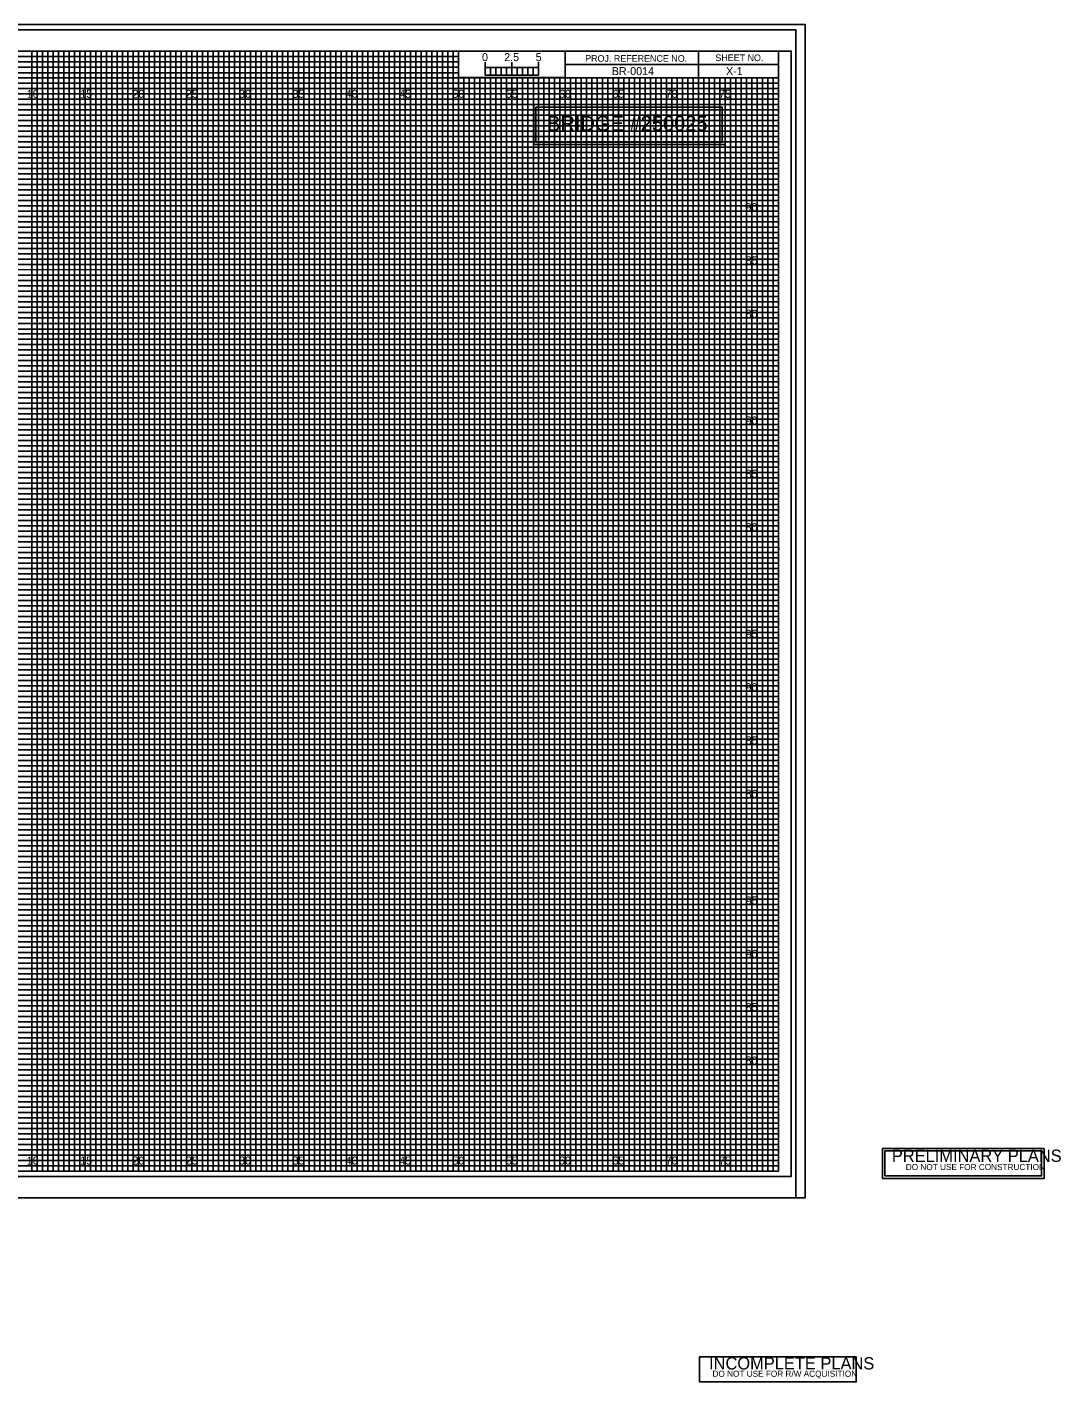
# Model space of a CAD drawing. Extents: x -8 to 533, y -20 to 768.
# Drawn here: x 89.5 to 186.5, y -19.8 to 107.2 of the extents above; entities that cross this region are included whole.
import ezdxf

# ---------------------------------------------------------------- set-up
doc = ezdxf.new("R2010")
doc.units = 0
for name, color, linetype in [('Old_Level_1', 7, 'Continuous'), ('Old_Level_34', 7, 'Continuous'), ('Prop Grid Mask', 7, 'Continuous'), ('Prop XS Bar Scale Labels', 7, 'Continuous'), ('Prop XS Elevation Labels', 7, 'Continuous'), ('Prop XS Offset Labels', 7, 'Continuous'), ('Prop XS Project Number', 7, 'Continuous'), ('Prop XS Sheet Number', 7, 'Continuous'), ('Sheet Cross Section CELL', 7, 'Continuous'), ('Sheet Cross Section Grid Major CELL', 7, 'Continuous'), ('Sheet Cross Section Grid Middle CELL', 7, 'Continuous'), ('Sheet Cross Section Grid Minor 1 CELL', 7, 'Continuous'), ('Sheet Cross Section Grid Minor 2 CELL', 7, 'Continuous'), ('Sheet Cross Section Scale CELL', 7, 'Continuous'), ('Sheet Cutting Line CELL', 7, 'Continuous'), ('Sheet DOT Grid CELL', 7, 'Continuous'), ('Sheet Plot Border Inside CELL', 7, 'Continuous'), ('Sheet Plot Border Outside CELL', 7, 'Continuous'), ('Sheet Sticker Incomplete CELL', 7, 'Continuous'), ('Sheet Sticker Preliminary CELL', 7, 'Continuous'), ('WEI Plot Border', 7, 'Continuous')]:
    doc.layers.add(name, color=color, linetype=linetype)

msp = doc.modelspace()

# ---------------------------------------------------------------- linework, layer by layer
at = {"layer": 'Old_Level_34'}
msp.add_lwpolyline([(137.26, 99.75), (154.74, 99.75), (154.74, 96.46), (137.26, 96.46)], close=True, dxfattribs=at)
at = {"layer": 'Prop Grid Mask'}
for points in [[(137.08, 100), (155, 100), (155, 96.24), (137.08, 96.24)], [(184.92, 2.13), (169.77, 2.13), (169.77, -0.7), (184.92, -0.7)]]:
    msp.add_lwpolyline(points, close=True, dxfattribs=at)
at = {"layer": 'Sheet Cross Section CELL'}
for p, q in [((152.5, 105), (152.5, 102.5)), ((152.5, 102.5), (152.5, 105)), ((160, 103.75), (140, 103.75)), ((140, 103.75), (140, 102.5)), ((140, 102.5), (160, 102.5))]:
    msp.add_line(p, q, dxfattribs=at)
for points in [[(160, 105), (0, 105), (0, 0), (160, 0)], [(140, 105), (130, 105), (130, 102.52), (140, 102.52)], [(160, 105), (140, 105), (140, 102.5), (160, 102.5)]]:
    msp.add_lwpolyline(points, close=True, dxfattribs=at)
at = {"layer": 'Sheet Cross Section Grid Major CELL'}
for p, q in [((95, 105), (90, 105)), ((90, 105), (90, 0)), ((95, 0), (95, 105)), ((105, 105), (100, 105)), ((100, 105), (100, 0)), ((105, 0), (105, 105)), ((115, 105), (110, 105)), ((110, 105), (110, 0)), ((115, 0), (115, 105)), ((125, 105), (120, 105)), ((120, 105), (120, 0)), ((125, 0), (125, 105)), ((130, 105), (130, 0)), ((135, 0), (135, 102.5)), ((145, 102.5), (140, 102.5)), ((140, 102.5), (140, 0)), ((145, 0), (145, 102.5)), ((155, 102.5), (150, 102.5)), ((150, 102.5), (150, 0)), ((155, 0), (155, 102.5)), ((90, 0), (85, 0)), ((100, 0), (95, 0)), ((110, 0), (105, 0)), ((120, 0), (115, 0)), ((130, 0), (125, 0)), ((140, 0), (135, 0)), ((150, 0), (145, 0)), ((160, 0), (155, 0)), ((160, 0), (160, 0))]:
    msp.add_line(p, q, dxfattribs=at)
for points in [[(0, 100), (160, 100), (160, 95), (0, 95)], [(0, 90), (160, 90), (160, 85), (0, 85)], [(0, 80), (160, 80), (160, 75), (0, 75)], [(0, 70), (160, 70), (160, 65), (0, 65)], [(0, 60), (160, 60), (160, 55), (0, 55)], [(0, 50), (160, 50), (160, 45), (0, 45)], [(0, 40), (160, 40), (160, 35), (0, 35)], [(0, 30), (160, 30), (160, 25), (0, 25)], [(0, 20), (160, 20), (160, 15), (0, 15)], [(0, 10), (160, 10), (160, 5), (0, 5)]]:
    msp.add_lwpolyline(points, dxfattribs=at)
at = {"layer": 'Sheet Cross Section Grid Middle CELL'}
for points in [[(87.5, 105), (92.5, 105), (92.5, 0), (97.5, 0), (97.5, 105), (102.5, 105), (102.5, 0), (107.5, 0), (107.5, 105), (112.5, 105), (112.5, 0), (117.5, 0), (117.5, 105), (122.5, 105), (122.5, 0), (127.5, 0), (127.5, 105), (129.97, 105), (130, 105), (130, 102.5), (132.5, 102.5), (132.5, 0), (137.5, 0), (137.5, 102.5), (142.5, 102.5), (142.5, 0), (147.5, 0), (147.5, 102.5), (152.5, 102.5), (152.5, 0), (157.5, 0), (157.5, 102.5)], [(0, 102.5), (137.5, 102.5)], [(0, 92.5), (160, 92.5), (160, 97.5), (0, 97.5)], [(0, 82.5), (160, 82.5), (160, 87.5), (0, 87.5)], [(0, 72.5), (160, 72.5), (160, 77.5), (0, 77.5)], [(0, 62.5), (160, 62.5), (160, 67.5), (0, 67.5)], [(0, 52.5), (160, 52.5), (160, 57.5), (0, 57.5)], [(0, 42.5), (160, 42.5), (160, 47.5), (0, 47.5)], [(0, 32.5), (160, 32.5), (160, 37.5), (0, 37.5)], [(0, 22.5), (160, 22.5), (160, 27.5), (0, 27.5)], [(0, 12.5), (160, 12.5), (160, 17.5), (0, 17.5)], [(0, 2.5), (160, 2.5), (160, 7.5), (0, 7.5)]]:
    msp.add_lwpolyline(points, dxfattribs=at)
at = {"layer": 'Sheet Cross Section Grid Minor 1 CELL'}
for p, q in [((0, 104.5), (130, 104.5)), ((130, 104.5), (130, 103.99)), ((130, 103.99), (0, 103.99)), ((0, 103.5), (130, 103.5)), ((130, 102.95), (0, 102.95)), ((130, 103.5), (130, 102.95)), ((0, 102), (160, 102))]:
    msp.add_line(p, q, dxfattribs=at)
for points in [[(0, 101.5), (135, 101.5), (160, 101.5), (160, 101), (0, 101)], [(0, 100.5), (160, 100.5), (160, 99.5), (0, 99.5)], [(0, 99), (160, 99), (160, 98.5), (0, 98.49)], [(0, 98), (160, 98), (160, 97), (0, 97)], [(0, 96.5), (160, 96.5), (160, 96), (0, 96)], [(0, 95.5), (160, 95.5), (160, 94.5), (0, 94.5)], [(0, 94), (160, 94), (160, 93.5), (0, 93.5)], [(0, 93), (160, 93), (160, 92), (0, 92)], [(0, 91.5), (160, 91.5), (160, 91), (0, 91)], [(0, 90.5), (160, 90.5), (160, 89.5), (0, 89.5)], [(0, 89), (160, 89), (160, 88.5), (0, 88.5)], [(0, 88), (160, 88), (160, 86.98), (160, 86.5), (160, 86), (0, 86)], [(0, 87), (160, 87), (160, 86.5), (0, 86.5)], [(0, 85.5), (160, 85.5), (160, 84.5), (0, 84.52)], [(0, 84.52), (160, 84.5), (160, 84), (0, 84)], [(0, 83.5), (160, 83.5), (160, 83), (0, 83)], [(0, 82), (160, 82), (160, 81.5), (0, 81.5)], [(0, 81), (160, 81), (160, 80.5), (0, 80.5)], [(-0.04, 79.45), (160, 79.45), (160, 78.94), (-0.04, 78.94)], [(0, 78.5), (160, 78.5), (160, 78), (0, 78)], [(0, 77), (160, 77), (160, 76.5), (0, 76.5)], [(0, 76), (160, 76), (160, 75.5), (0, 75.5)], [(0, 74.5), (160, 74.5), (160, 74), (0, 74)], [(0, 73.5), (160, 73.5), (160, 73), (0, 73)], [(0, 72), (160, 72), (160, 71.5), (0, 71.5)], [(0, 71), (160, 71), (160, 70.5), (0, 70.5)], [(0, 69.5), (160, 69.5), (160, 68.99), (0, 69)], [(0, 68.5), (160, 68.5), (160, 68), (0, 68)], [(0, 67), (160, 67), (160, 66.5), (0, 66.5)], [(0, 66), (160, 66), (160, 65.5), (0, 65.5)], [(0, 64.5), (160, 64.5), (160, 64), (0, 64)], [(0, 63.5), (160, 63.5), (160, 63), (0, 63)], [(0, 62), (160, 62), (160, 61.5), (0, 61.5)], [(0, 61), (160, 61), (160, 60.5), (0, 60.5)], [(0, 59.5), (160, 59.5), (160, 59), (0, 59)], [(0, 58.5), (160.03, 58.45), (160, 58), (0, 58)], [(0, 57), (160, 57), (160, 56.5), (0, 56.5)], [(0, 56), (160, 56), (160, 55.5), (0, 55.5)], [(0, 54.5), (160, 54.5), (160, 54), (0, 54)], [(0, 53.5), (160, 53.5), (160, 53), (0, 53)], [(0, 52), (160, 52), (160, 51.5), (0, 51.5)], [(0, 51), (160, 51), (160, 50.5), (0, 50.5)], [(0, 49.5), (160, 49.5), (160, 49), (0, 49)], [(0, 48.5), (160, 48.5), (160, 48), (0, 48)], [(0, 47), (160, 47), (160, 46.5), (0, 46.5)], [(0, 46), (160, 46), (160, 45.5), (0, 45.5)], [(0, 44.5), (160, 44.5), (160, 44), (0, 44)], [(0, 43.5), (160, 43.5), (160, 43), (0, 43)], [(0, 42), (160, 42), (160, 41.5), (0, 41.5)], [(0, 41), (160, 41), (160, 40.5), (0, 40.5)], [(0, 39.5), (160, 39.5), (160, 38.99), (0, 39)], [(0, 38.5), (160, 38.5), (160, 38), (0, 38)], [(0, 37), (160, 37), (160, 36.5), (0, 36.5)], [(0, 36), (160, 36), (160, 35.5), (0, 35.5)], [(0, 34.5), (160, 34.5), (160, 34), (0, 34)], [(0, 33.5), (160, 33.5), (160, 33), (0, 33)], [(0, 32), (160, 32), (160, 31.5), (0, 31.5)], [(0, 31), (160, 31), (160, 30.5), (0, 30.5)], [(0, 29.5), (160, 29.5), (160, 29), (0, 29)], [(0, 28.5), (160.03, 28.46), (160, 28), (0, 28)], [(0, 27), (160, 27), (160, 26.5), (0, 26.5)], [(0, 26), (160, 26), (160, 25.5), (0, 25.5)], [(0, 24.5), (160, 24.5), (160, 24), (0, 24)], [(0, 23.5), (160, 23.5), (160, 23), (0, 23)], [(0, 22), (160, 22), (160, 21.5), (0, 21.5)], [(0, 21), (160, 21), (160, 20.5), (0, 20.5)], [(0, 19.5), (160, 19.5), (160, 19), (0, 19)], [(0, 18.5), (160, 18.5), (160, 18), (0, 18)], [(0, 17), (160, 17), (160, 16.5), (0, 16.5)], [(0, 16), (160, 16), (160, 15.5), (0, 15.5)], [(0, 14.5), (160, 14.5), (160, 14), (0, 14)], [(0, 13.5), (160, 13.5), (160, 13), (0, 13)], [(0, 12), (160, 12), (160, 11.5), (0, 11.5)], [(0, 11), (160, 11), (160, 10.5), (0, 10.5)], [(0, 9.5), (160, 9.5), (160, 9), (0, 9)], [(0, 8.5), (160, 8.5), (160, 8), (0, 8)], [(0, 7), (160, 7), (160, 6.5), (0, 6.5)], [(0, 6), (160, 6), (160, 5.5), (0, 5.5)], [(0, 4.5), (160, 4.5), (160, 4), (0, 4)], [(0, 3.5), (160, 3.5), (160, 3), (0, 3)], [(0, 2), (160, 2), (160, 1.5), (0, 1.5)], [(0, 1), (160, 1), (160, 0.5), (0, 0.5)]]:
    msp.add_lwpolyline(points, dxfattribs=at)
at = {"layer": 'Sheet Cross Section Grid Minor 2 CELL'}
for p, q in [((133.5, 102.5), (133, 102.5)), ((133, 102.5), (133, 0)), ((133.5, 0), (133.5, 102.5)), ((134.5, 102.5), (134, 102.5)), ((134, 102.5), (134, 0)), ((134.5, 0), (134.5, 102.5)), ((133, 0), (132.5, 0)), ((134, 0), (133.5, 0))]:
    msp.add_line(p, q, dxfattribs=at)
for points in [[(90, 0), (90.5, 0), (90.5, 105), (91, 105), (91, 0)], [(91, 0), (91.5, 0), (91.5, 105), (92, 105), (92, 0)], [(92.5, 0), (93, 0), (93, 105), (93.5, 105), (93.5, 0)], [(93.5, 0), (94, 0), (94, 105), (94.5, 105), (94.5, 0)], [(95, 0), (95.5, 0), (95.5, 105), (96, 105), (96, 0)], [(96, 0), (96.5, 0), (96.5, 105), (97, 105), (97, 0)], [(97.5, 0), (98, 0), (98, 105), (98.5, 105), (98.5, 0)], [(98.5, 0), (99, 0), (99, 105), (99.5, 105), (99.5, 0)], [(100, 0), (100.5, 0), (100.5, 105), (101, 105), (101, 0)], [(101, 0), (101.5, 0), (101.5, 105), (102, 105), (102, 0)], [(102.5, 0), (103, 0), (103, 105), (103.5, 105), (103.5, 0)], [(103.5, 0), (104, 0), (104, 105), (104.5, 105), (104.5, 0)], [(105, 0), (105.5, 0), (105.5, 105), (106, 105), (106, 0)], [(106, 0), (106.5, 0), (106.5, 105), (107, 105), (107, 0)], [(107.5, 0), (108, 0), (108, 105), (108.5, 105), (108.5, 0)], [(108.5, 0), (109, 0), (109, 105), (109.5, 105), (109.5, 0)], [(110, 0), (110.5, 0), (110.5, 105), (111, 105), (111, 0)], [(111, 0), (111.5, 0), (111.5, 105), (112, 105), (112, 0)], [(112.5, 0), (113, 0), (113, 105), (113.5, 105), (113.5, 0)], [(113.5, 0), (114, 0), (114, 105), (114.5, 105), (114.5, 0)], [(115, 0), (115.5, 0), (115.5, 105), (116, 105), (116, 0)], [(116, 0), (116.5, 0), (116.5, 105), (117, 105), (117, 0)], [(117.5, 0), (118, 0), (118, 105), (118.5, 105), (118.5, 0)], [(118.5, 0), (119, 0), (119, 105), (119.5, 105), (119.5, 0)], [(120, 0), (120.5, 0), (120.5, 105), (121, 105), (121, 0)], [(121, 0), (121.5, 0), (121.5, 105), (122, 105), (122, 0)], [(122.5, 0), (123, 0), (123, 105), (123.5, 105), (123.5, 0)], [(123.5, 0), (124, 0), (124, 105), (124.5, 105), (124.5, 0)], [(125, 0), (125.5, 0), (125.5, 105), (126, 105), (126, 0)], [(126, 0), (126.5, 0), (126.5, 105), (127, 105), (127, 0)], [(127.5, 0), (128, 0), (128, 105), (128.5, 105), (128.5, 0)], [(128.5, 0), (129, 0), (129, 105), (129.5, 105), (129.5, 0)], [(130, 0), (130.5, 0), (130.5, 102.5), (131.01, 102.5), (131.01, 0)], [(131, 0), (131.5, 0), (131.5, 102.5), (132, 102.5), (132, 0)], [(135, 0), (135.49, 0), (135.49, 102.5), (136, 102.5), (136, 0)], [(136, 0), (136.5, 0), (136.5, 102.5), (137.03, 102.5), (137.03, 0)], [(137.5, 0), (138, 0), (138, 102.5), (138.5, 102.5), (138.5, 0)], [(138.5, 0), (139, 0), (139, 102.5), (139.5, 102.5), (139.5, 0)], [(140, 0), (140.5, 0), (140.5, 102.5), (141, 102.5), (141, 0)], [(141, 0), (141.5, 0), (141.5, 102.5), (142, 102.5), (142, 0)], [(142.5, 0), (143, 0), (143, 102.5), (143.5, 102.5), (143.5, 0)], [(143.5, 0), (144, 0), (144, 102.5), (144.5, 102.5), (144.5, 0)], [(145, 0), (145.5, 0), (145.5, 102.5), (146, 102.5), (146, 0)], [(146, 0), (146.5, 0), (146.5, 102.5), (147, 102.5), (147, 0)], [(147.5, 0), (148, 0), (148, 102.5), (148.5, 102.5), (148.5, 0)], [(148.5, 0), (149, 0), (149, 102.5), (149.5, 102.5), (149.5, 0)], [(150, 0), (150.5, 0), (150.5, 102.5), (151, 102.5), (151, 0)], [(151, 0), (151.5, 0), (151.5, 102.5), (152, 102.5), (152, 0)], [(152.5, 0), (153, 0), (153, 102.5), (153.5, 102.5), (153.5, 0)], [(153.5, 0), (154, 0), (154, 102.5), (154.5, 102.5), (154.5, 0)], [(155, 0), (155.5, 0), (155.5, 102.5), (156, 102.5), (156, 0)], [(156, 0), (156.5, 0), (156.5, 102.5), (157, 102.5), (157, 0)], [(157.5, 0), (158, 0), (158, 102.5), (158.5, 102.5), (158.5, 0)], [(158.5, 0), (159, 0), (159, 102.5), (159.5, 102.5), (159.5, 0)]]:
    msp.add_lwpolyline(points, dxfattribs=at)
at = {"layer": 'Sheet Cross Section Scale CELL'}
for p, q in [((132.5, 102.75), (132.5, 103.95)), ((132.5, 103.45), (132.5, 103.95)), ((135, 102.75), (135, 103.95)), ((137.5, 102.75), (137.5, 103.95)), ((137.5, 103.45), (137.5, 103.95))]:
    msp.add_line(p, q, dxfattribs=at)
for points in [[(137.5, 103.45), (132.5, 103.45), (132.5, 102.75), (137.5, 102.75)], [(132.5, 103.45), (133, 103.45), (133, 102.75), (132.5, 102.75)], [(133.5, 103.45), (134, 103.45), (134, 102.75), (133.5, 102.75)], [(134.5, 103.45), (135, 103.45), (135, 102.75), (134.5, 102.75)], [(135.5, 103.45), (136, 103.45), (136, 102.75), (135.5, 102.75)], [(136.5, 103.45), (137, 103.45), (137, 102.75), (136.5, 102.75)]]:
    msp.add_lwpolyline(points, close=True, dxfattribs=at)
at = {"layer": 'Sheet Cutting Line CELL'}
for p, q in [((161.65, 107), (-6.7, 107)), ((-6.7, -2.5), (161.65, -2.5))]:
    msp.add_line(p, q, dxfattribs=at)
at = {"layer": 'Sheet DOT Grid CELL'}
for p, q in [((90, 0), (90, 105)), ((95, 0), (95, 105)), ((100, 0), (100, 105)), ((105, 0), (105, 105)), ((110, 0), (110, 105)), ((115, 0), (115, 105)), ((120, 0), (120, 105)), ((125, 0), (125, 105)), ((130, 0), (130, 102.34)), ((135, 0), (135, 102.34)), ((140, 0), (140, 102.34)), ((145, 0), (145, 102.34)), ((150, 0), (150, 102.34)), ((155, 0), (155, 102.34)), ((0, 100), (160, 100)), ((0, 95), (160, 95)), ((0, 90), (160, 90)), ((0, 85), (160, 85)), ((0, 80), (160, 80)), ((0, 75), (160, 75)), ((0, 70), (160, 70)), ((0, 65), (160, 65)), ((0, 60), (160, 60)), ((0, 55), (160, 55)), ((0, 50), (160, 50)), ((0, 45), (160, 45)), ((0, 40), (160, 40)), ((0, 35), (160, 35)), ((0, 30), (160, 30)), ((0, 25), (160, 25)), ((0, 20), (160, 20)), ((0, 15), (160, 15)), ((0, 10), (160, 10)), ((0, 5), (160, 5))]:
    msp.add_line(p, q, dxfattribs=at)
at = {"layer": 'Sheet Plot Border Inside CELL'}
msp.add_lwpolyline([(-5.4, -0.5), (161.2, -0.5), (161.2, 105), (-5.4, 105)], close=True, dxfattribs=at)
at = {"layer": 'Sheet Plot Border Outside CELL'}
msp.add_lwpolyline([(-6.7, -2.5), (161.65, -2.5), (161.65, 107), (-6.7, 107)], close=True, dxfattribs=at)
at = {"layer": 'Sheet Sticker Incomplete CELL'}
msp.add_lwpolyline([(152.6, -19.76), (152.6, -17.41), (167.3, -17.41), (167.3, -19.76)], close=True, dxfattribs=at)
at = {"layer": 'Sheet Sticker Preliminary CELL'}
msp.add_lwpolyline([(169.99, -0.45), (169.99, 1.9), (184.69, 1.9), (184.69, -0.45)], close=True, dxfattribs=at)
at = {"layer": 'WEI Plot Border'}
msp.add_lwpolyline([(-7.5, -2.5), (162.5, -2.5), (162.5, 107.5), (-7.5, 107.5)], close=True, dxfattribs=at)

# ---------------------------------------------------------------- texts
at = {"layer": 'Old_Level_1'}
msp.add_text('BRIDGE #250025', height=1.4062, rotation=360, dxfattribs=at).set_placement((138.31, 97.52))
at = {"layer": 'Prop XS Bar Scale Labels'}
for s, p in [('2.5', (134.29, 104.06)), ('5', (137.24, 104.06))]:
    msp.add_text(s, height=0.75, dxfattribs=at).set_placement(p)
at = {"layer": 'Prop XS Elevation Labels'}
for s, p in [('90', (156.93, 90)), ('85', (156.94, 85)), ('80', (156.93, 80)), ('90', (156.93, 70)), ('85', (156.94, 65)), ('80', (156.93, 60)), ('95', (156.94, 50)), ('90', (156.93, 45)), ('85', (156.94, 40)), ('80', (156.93, 35)), ('95', (156.94, 25)), ('90', (156.93, 20)), ('85', (156.94, 15)), ('80', (156.93, 10))]:
    msp.add_text(s, height=0.75, dxfattribs=at).set_placement(p)
at = {"layer": 'Prop XS Offset Labels'}
for s, p in [('10', (89.52, 100.62)), ('15', (94.53, 100.62)), ('20', (99.43, 100.62)), ('25', (104.44, 100.62)), ('30', (109.43, 100.62)), ('35', (114.44, 100.62)), ('40', (119.43, 100.62)), ('45', (124.44, 100.62)), ('50', (129.43, 100.62)), ('55', (134.44, 100.62)), ('60', (139.43, 100.62)), ('65', (144.44, 100.62)), ('70', (149.43, 100.62)), ('75', (154.44, 100.62)), ('10', (89.52, 0.62)), ('15', (94.53, 0.62)), ('20', (99.43, 0.62)), ('25', (104.44, 0.62)), ('30', (109.43, 0.62)), ('35', (114.44, 0.62)), ('40', (119.43, 0.62)), ('45', (124.44, 0.62)), ('50', (129.43, 0.62)), ('55', (134.44, 0.62)), ('60', (139.43, 0.62)), ('65', (144.44, 0.62)), ('70', (149.43, 0.62)), ('75', (154.44, 0.62))]:
    msp.add_text(s, height=0.75, dxfattribs=at).set_placement(p)
at = {"layer": 'Prop XS Project Number'}
msp.add_text('BR-0014', height=0.75, dxfattribs=at).set_placement((144.38, 102.75))
at = {"layer": 'Prop XS Sheet Number'}
msp.add_text('X-1', height=0.75, dxfattribs=at).set_placement((155.09, 102.75))
at = {"layer": 'Sheet Cross Section CELL'}
for s, p in [('PROJ. REFERENCE NO.', (141.88, 104)), ('SHEET NO.', (154.09, 104.06))]:
    msp.add_text(s, height=0.625, dxfattribs=at).set_placement(p)
at = {"layer": 'Sheet Cross Section Scale CELL'}
msp.add_text('0', height=0.75, dxfattribs=at).set_placement((132.21, 104.06))
at = {"layer": 'Sheet Sticker Incomplete CELL'}
for s, height, p in [('INCOMPLETE PLANS', 1.152, (153.5, -18.59)), ('DO NOT USE FOR R/W ACQUISITION', 0.576, (153.82, -19.28))]:
    msp.add_text(s, height=height, dxfattribs=at).set_placement(p)
at = {"layer": 'Sheet Sticker Preliminary CELL'}
for s, height, p in [('PRELIMINARY PLANS', 1.152, (170.64, 0.87)), ('DO NOT USE FOR CONSTRUCTION', 0.576, (171.95, 0.1))]:
    msp.add_text(s, height=height, dxfattribs=at).set_placement(p)

doc.saveas('drawing.dxf')
